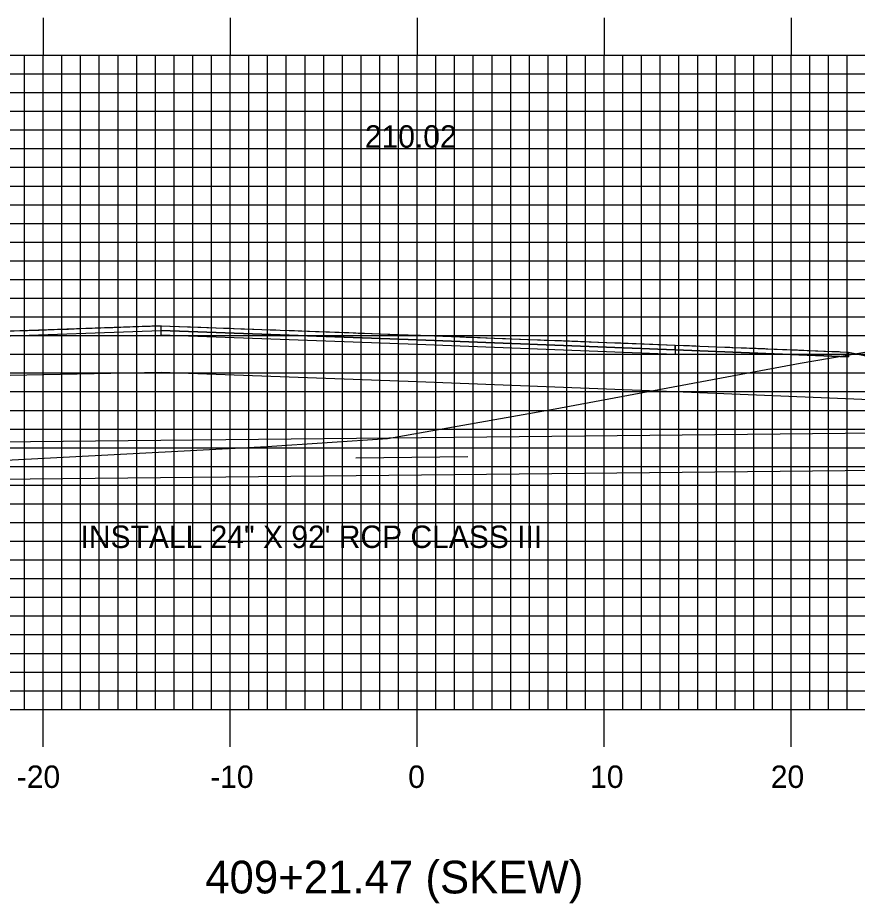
# Model space of a CAD drawing. Extents: x 852922 to 853266, y 364785 to 365005.
# Drawn here: x 853066.88 to 853111.78, y 364847.86 to 364895.24 of the extents above; entities that cross this region are included whole.
import ezdxf

# ---------------------------------------------------------------- set-up
doc = ezdxf.new("R2010")
doc.units = 0
for name, color, linetype in [('D_Drainage_Culvert', 7, 'Continuous'), ('D_Drainage_Text', 7, 'Continuous'), ('D_Roadway_Centerline', 7, 'Continuous'), ('D_Roadway_Centerline_Text', 7, 'Continuous'), ('D_Roadway_Edge_Shoulder', 7, 'Continuous'), ('D_Roadway_Edge_TW', 7, 'Continuous'), ('D_Roadway_Pavement', 7, 'Continuous'), ('D_Roadway_SubGrade', 7, 'Continuous'), ('H_V ANNOTATION', 7, 'Continuous'), ('MAJOR', 7, 'Continuous'), ('MINOR', 7, 'Continuous'), ('S_Roadway_Centerline', 7, 'Continuous')]:
    doc.layers.add(name, color=color, linetype=linetype)

msp = doc.modelspace()

# ---------------------------------------------------------------- linework, layer by layer
at = {"layer": 'D_Drainage_Culvert'}
for p, q in [((853038.024, 364872.279), (853130.019, 364873.199)), ((853090.955, 364871.743), (853084.955, 364871.683)), ((853038.044, 364870.279), (853130.039, 364871.199))]:
    msp.add_line(p, q, dxfattribs=at)
at = {"layer": 'D_Roadway_Centerline'}
msp.add_lwpolyline([(853065.823, 364878.448), (853067.114, 364878.495), (853067.396, 364878.505), (853067.862, 364878.521), (853068.027, 364878.527), (853068.821, 364878.555), (853069.28, 364878.571), (853069.419, 364878.576), (853069.602, 364878.583), (853069.9, 364878.593), (853070.215, 364878.604), (853070.86, 364878.627), (853071.79, 364878.659), (853071.962, 364878.666), (853072.387, 364878.68), (853073.839, 364878.731), (853073.963, 364878.735), (853074.543, 364878.755), (853075.959, 364878.704), (853076.119, 364878.698), (853076.599, 364878.681), (853076.682, 364878.678), (853077.882, 364878.635), (853078.259, 364878.621), (853078.412, 364878.615), (853078.806, 364878.601), (853078.946, 364878.596), (853079.011, 364878.594), (853079.502, 364878.575), (853080.384, 364878.544), (853080.68, 364878.533), (853080.915, 364878.524), (853081.68, 364878.497), (853082.493, 364878.466), (853082.801, 364878.455), (853083.009, 364878.447), (853083.557, 364878.428), (853084.587, 364878.389), (853084.965, 364878.375), (853085.087, 364878.37), (853085.418, 364878.358), (853086.666, 364878.312), (853087.109, 364878.295), (853087.15, 364878.294), (853088.244, 364878.253), (853088.425, 364878.246), (853088.72, 364878.235), (853088.73, 364878.234), (853088.747, 364878.234), (853089.199, 364878.217), (853090.523, 364878.167), (853090.779, 364878.157), (853090.864, 364878.154), (853091.233, 364878.14), (853092.351, 364878.098), (853092.813, 364878.08), (853092.962, 364878.074), (853093.253, 364878.063), (853094.164, 364878.029), (853094.833, 364878.003), (853095.04, 364877.995), (853095.258, 364877.986), (853095.964, 364877.96), (853096.839, 364877.926), (853096.992, 364877.92), (853097.249, 364877.91), (853097.442, 364877.902), (853097.54, 364877.898), (853097.931, 364877.884), (853098.831, 364877.848), (853099.142, 364877.836), (853099.227, 364877.833), (853099.522, 364877.822), (853100.809, 364877.771), (853100.843, 364877.77), (853101.191, 364877.756), (853102.048, 364877.723), (853102.773, 364877.694), (853102.802, 364877.693), (853103.141, 364877.68), (853103.364, 364877.671), (853104.723, 364877.617), (853104.967, 364877.608), (853105.078, 364877.603), (853105.846, 364877.573), (853106.371, 364877.552), (853106.509, 364877.546), (853106.66, 364877.54), (853106.835, 364877.533), (853107.001, 364877.527), (853108.017, 364877.486), (853108.584, 364877.463), (853108.823, 364877.454), (853108.912, 364877.45), (853109.266, 364877.436), (853110.494, 364877.386), (853110.791, 364877.374), (853110.809, 364877.374), (853110.884, 364877.371), (853111.313, 364877.353), (853112.287, 364877.144)], dxfattribs=at)
at = {"layer": 'D_Roadway_Edge_Shoulder'}
for points in [[(853074.544, 364878.755), (853065.463, 364878.436), (853065.463, 364878.186), (853074.544, 364878.505)], [(853102.048, 364877.723), (853111.313, 364877.353), (853111.313, 364877.103), (853102.048, 364877.473)]]:
    msp.add_lwpolyline(points, close=True, dxfattribs=at)
at = {"layer": 'D_Roadway_Edge_TW'}
msp.add_lwpolyline([(853074.544, 364878.505), (853074.544, 364878.755), (853088.244, 364878.253), (853102.048, 364877.723), (853102.048, 364877.473), (853088.244, 364878.003)], close=True, dxfattribs=at)
at = {"layer": 'D_Roadway_Pavement'}
msp.add_lwpolyline([(853074.544, 364878.255), (853074.544, 364878.505), (853088.244, 364878.003), (853102.048, 364877.473), (853102.048, 364877.223), (853088.244, 364877.753)], close=True, dxfattribs=at)
at = {"layer": 'D_Roadway_SubGrade'}
msp.add_lwpolyline([(853074.544, 364876.255), (853053.898, 364875.841), (853065.463, 364878.436), (853065.463, 364878.186), (853074.544, 364878.505), (853088.244, 364878.003), (853102.048, 364877.473), (853111.313, 364877.103), (853111.313, 364877.353), (853122.88, 364874.9), (853122.88, 364874.372), (853102.048, 364875.223), (853088.244, 364875.753)], close=True, dxfattribs=at)
at = {"layer": 'MAJOR'}
for p, q in [((853068.244, 364895.237), (853068.244, 364893.233)), ((853078.244, 364895.237), (853078.244, 364893.233)), ((853088.244, 364895.237), (853088.244, 364893.233)), ((853098.244, 364895.237), (853098.244, 364893.233)), ((853108.244, 364895.237), (853108.244, 364893.233)), ((852948.244, 364893.233), (853228.244, 364893.233)), ((852948.244, 364893.233), (853228.244, 364893.233)), ((853068.244, 364858.233), (853068.244, 364893.233)), ((853078.244, 364858.233), (853078.244, 364893.233)), ((853088.244, 364858.233), (853088.244, 364893.233)), ((853098.244, 364858.233), (853098.244, 364893.233)), ((853108.244, 364858.233), (853108.244, 364893.233)), ((852948.244, 364888.233), (853228.244, 364888.233)), ((852948.244, 364883.233), (853228.244, 364883.233)), ((852948.244, 364878.233), (853228.244, 364878.233)), ((852948.244, 364873.233), (853228.244, 364873.233)), ((852948.244, 364868.233), (853228.244, 364868.233)), ((852948.244, 364863.233), (853228.244, 364863.233)), ((852948.244, 364858.233), (853228.244, 364858.233)), ((852948.244, 364858.233), (853228.244, 364858.233)), ((853068.244, 364856.229), (853068.244, 364858.233)), ((853078.244, 364856.229), (853078.244, 364858.233)), ((853088.244, 364856.229), (853088.244, 364858.233)), ((853098.244, 364856.229), (853098.244, 364858.233)), ((853108.244, 364856.229), (853108.244, 364858.233))]:
    msp.add_line(p, q, dxfattribs=at)
at = {"layer": 'MINOR'}
for p, q in [((853067.244, 364858.233), (853067.244, 364893.233)), ((853069.244, 364858.233), (853069.244, 364893.233)), ((853070.244, 364858.233), (853070.244, 364893.233)), ((853071.244, 364858.233), (853071.244, 364893.233)), ((853072.244, 364858.233), (853072.244, 364893.233)), ((853073.244, 364858.233), (853073.244, 364893.233)), ((853074.244, 364858.233), (853074.244, 364893.233)), ((853075.244, 364858.233), (853075.244, 364893.233)), ((853076.244, 364858.233), (853076.244, 364893.233)), ((853077.244, 364858.233), (853077.244, 364893.233)), ((853079.244, 364858.233), (853079.244, 364893.233)), ((853080.244, 364858.233), (853080.244, 364893.233)), ((853081.244, 364858.233), (853081.244, 364893.233)), ((853082.244, 364858.233), (853082.244, 364893.233)), ((853083.244, 364858.233), (853083.244, 364893.233)), ((853084.244, 364858.233), (853084.244, 364893.233)), ((853085.244, 364858.233), (853085.244, 364893.233)), ((853086.244, 364858.233), (853086.244, 364893.233)), ((853087.244, 364858.233), (853087.244, 364893.233)), ((853089.244, 364858.233), (853089.244, 364893.233)), ((853090.244, 364858.233), (853090.244, 364893.233)), ((853091.244, 364858.233), (853091.244, 364893.233)), ((853092.244, 364858.233), (853092.244, 364893.233)), ((853093.244, 364858.233), (853093.244, 364893.233)), ((853094.244, 364858.233), (853094.244, 364893.233)), ((853095.244, 364858.233), (853095.244, 364893.233)), ((853096.244, 364858.233), (853096.244, 364893.233)), ((853097.244, 364858.233), (853097.244, 364893.233)), ((853099.244, 364858.233), (853099.244, 364893.233)), ((853100.244, 364858.233), (853100.244, 364893.233)), ((853101.244, 364858.233), (853101.244, 364893.233)), ((853102.244, 364858.233), (853102.244, 364893.233)), ((853103.244, 364858.233), (853103.244, 364893.233)), ((853104.244, 364858.233), (853104.244, 364893.233)), ((853105.244, 364858.233), (853105.244, 364893.233)), ((853106.244, 364858.233), (853106.244, 364893.233)), ((853107.244, 364858.233), (853107.244, 364893.233)), ((853109.244, 364858.233), (853109.244, 364893.233)), ((853110.244, 364858.233), (853110.244, 364893.233)), ((853111.244, 364858.233), (853111.244, 364893.233)), ((852948.244, 364892.233), (853228.244, 364892.233)), ((852948.244, 364891.233), (853228.244, 364891.233)), ((852948.244, 364890.233), (853228.244, 364890.233)), ((852948.244, 364889.233), (853228.244, 364889.233)), ((852948.244, 364887.233), (853228.244, 364887.233)), ((852948.244, 364886.233), (853228.244, 364886.233)), ((852948.244, 364885.233), (853228.244, 364885.233)), ((852948.244, 364884.233), (853228.244, 364884.233)), ((852948.244, 364882.233), (853228.244, 364882.233)), ((852948.244, 364881.233), (853228.244, 364881.233)), ((852948.244, 364880.233), (853228.244, 364880.233)), ((852948.244, 364879.233), (853228.244, 364879.233)), ((852948.244, 364877.233), (853228.244, 364877.233)), ((852948.244, 364876.233), (853228.244, 364876.233)), ((852948.244, 364875.233), (853228.244, 364875.233)), ((852948.244, 364874.233), (853228.244, 364874.233)), ((852948.244, 364872.233), (853228.244, 364872.233)), ((852948.244, 364871.233), (853228.244, 364871.233)), ((852948.244, 364870.233), (853228.244, 364870.233)), ((852948.244, 364869.233), (853228.244, 364869.233)), ((852948.244, 364867.233), (853228.244, 364867.233)), ((852948.244, 364866.233), (853228.244, 364866.233)), ((852948.244, 364865.233), (853228.244, 364865.233)), ((852948.244, 364864.233), (853228.244, 364864.233)), ((852948.244, 364862.233), (853228.244, 364862.233)), ((852948.244, 364861.233), (853228.244, 364861.233)), ((852948.244, 364860.233), (853228.244, 364860.233)), ((852948.244, 364859.233), (853228.244, 364859.233))]:
    msp.add_line(p, q, dxfattribs=at)
at = {"layer": 'S_Roadway_Centerline'}
msp.add_lwpolyline([(852948.244, 364867.115), (852952.293, 364867.224), (852982.811, 364869.572), (852983.433, 364869.613), (852984.764, 364869.671), (852995.961, 364869.609), (853002.177, 364870.032), (853019.783, 364870.025), (853022.004, 364870.134), (853031.206, 364870.205), (853040.954, 364870.271), (853047.088, 364870.613), (853061.473, 364871.309), (853080.196, 364872.293), (853086.656, 364872.726), (853095.621, 364874.314), (853108.715, 364876.755), (853119.923, 364878.669), (853126.685, 364878.29), (853138.551, 364878.414), (853139.241, 364878.439), (853141.359, 364878.394), (853158.491, 364878.3)], dxfattribs=at)

# ---------------------------------------------------------------- texts
at = {"layer": 'D_Drainage_Text'}
msp.add_text('INSTALL 24" X 92\' RCP CLASS III', height=1.2, dxfattribs=at).set_placement((853070.24, 364866.869))
at = {"layer": 'D_Roadway_Centerline_Text'}
msp.add_text('210.02', height=1.2, dxfattribs=at).set_placement((853085.445, 364888.283))
at = {"layer": 'H_V ANNOTATION'}
for s, height, p in [('-20', 1.2, (853066.831, 364854.033)), ('-10', 1.2, (853077.174, 364854.033)), ('0', 1.2, (853087.762, 364854.033)), ('10', 1.2, (853097.494, 364854.033)), ('20', 1.2, (853107.152, 364854.033)), ('409+21.47 (SKEW)', 1.74996, (853076.905, 364848.389))]:
    msp.add_text(s, height=height, dxfattribs=at).set_placement(p)

doc.saveas('drawing.dxf')
